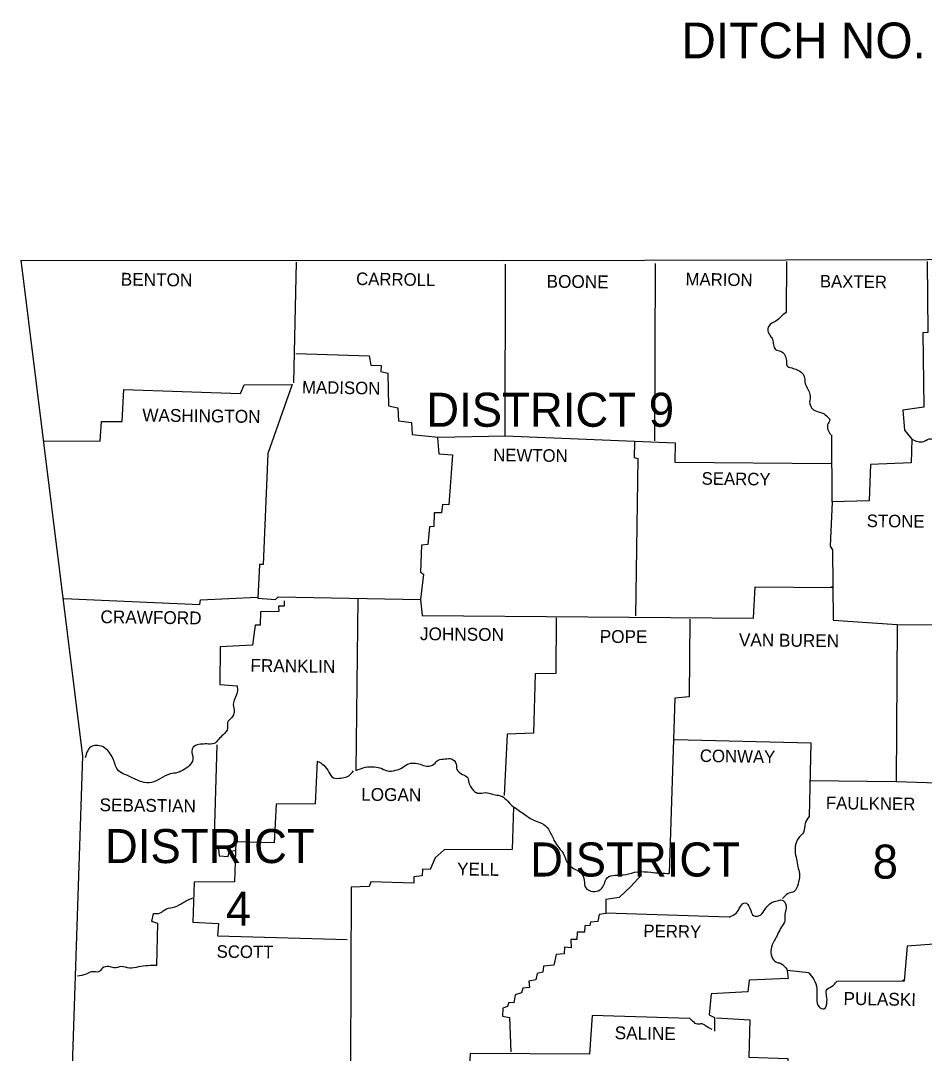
# Model space of a CAD drawing. Extents: x 191 to 3403, y 68 to 2102.
# Drawn here: x 2703.7 to 2999.8, y 1696.4 to 2035 of the extents above; entities that cross this region are included whole.
import ezdxf

# ---------------------------------------------------------------- set-up
doc = ezdxf.new("R2010")
doc.units = 0
for name, color, linetype in [('1', 7, 'Continuous'), ('2', 7, 'Continuous'), ('3', 7, 'Continuous'), ('R_Border', 7, 'Continuous')]:
    doc.layers.add(name, color=color, linetype=linetype)

msp = doc.modelspace()

# ---------------------------------------------------------------- linework, layer by layer
at = {"layer": '1'}
for points in [[(2703.71, 1956.42), (2861.92, 1956.32), (3000.75, 1956.61), (3164.54, 1959.16), (3240.46, 1960.92)], [(2703.71, 1956.42), (2723.96, 1793.81), (2715.15, 1528.37)], [(2794.01, 1955.83), (2793.13, 1916.21)], [(2793.82, 1925.89), (2817.89, 1925.11), (2818.47, 1921.98), (2821.8, 1921.88), (2821.7, 1919.92), (2824.05, 1919.34), (2824.25, 1908.67), (2827.28, 1907.99), (2827.48, 1903.78), (2831.78, 1903.19), (2831.98, 1899.28), (2840.49, 1898.4), (2862.4, 1898.89), (2862.6, 1955.15)], [(2911.62, 1955.34), (2911.33, 1897.22)], [(2954.67, 1956.03), (2954.47, 1939.3)], [(3000.75, 1956.03), (3000.95, 1932.74), (2999.28, 1932.64), (2999.58, 1908.28), (2992.73, 1907.3), (2993.32, 1900.75), (2995.66, 1897.71), (2995.47, 1889.98), (2982.16, 1889.5), (2981.67, 1877.56), (2969.54, 1877.17), (2968.95, 1862.69), (2969.64, 1861.51), (2969.93, 1838.42), (2990.87, 1837.05), (2990.58, 1785.49), (3007.21, 1785), (3007.21, 1732.56), (2994.1, 1731.58), (2993.12, 1720.04), (2971.11, 1719.94)], [(2711.44, 1897.22), (2729.73, 1897.13), (2730.22, 1903.58), (2736.97, 1903.58), (2737.56, 1914.05), (2775.72, 1912.68), (2776.89, 1915.62), (2792.64, 1915.72), (2784.72, 1893.02), (2783.15, 1856.72), (2781.98, 1856.62), (2781.39, 1845.66), (2787.17, 1845.17), (2788.05, 1846.05), (2834.72, 1845.17), (2835.21, 1839.99)], [(2840.29, 1898.2), (2840.68, 1892.92), (2845.18, 1892.63), (2844.01, 1876.19), (2841.96, 1876.29), (2841.56, 1873.65), (2839.22, 1873.65), (2839.12, 1869.14), (2837.65, 1869.05), (2837.16, 1863.27), (2835.01, 1862.98), (2834.72, 1854.17), (2835.69, 1853.49), (2834.72, 1845.17)], [(2862.4, 1898.89), (2918.17, 1896.54), (2918.08, 1890.18), (2969.25, 1889.79)], [(2904.77, 1896.83), (2904.67, 1891.75), (2905.94, 1891.45), (2905.16, 1839.79)], [(2969.54, 1877.17), (2969.44, 1899.18)], [(2835.21, 1839.99), (2943.81, 1839.11), (2944.3, 1849.38), (2969.54, 1849.09)], [(2969.25, 1849.19), (2969.54, 1849.48)], [(2717.89, 1845.56), (2762.41, 1843.51), (2762.61, 1845.08), (2781.2, 1845.96)], [(2814.17, 1845.56), (2813.48, 1789.11)], [(2790, 1844.78), (2790, 1843.02), (2788.14, 1843.02), (2788.24, 1841.26), (2782.27, 1841.16), (2782.18, 1836.76), (2780.51, 1836.76), (2779.63, 1830.2), (2769.06, 1829.71), (2768.97, 1817.29), (2774.64, 1816.9)], [(2879.14, 1839.21), (2879.04, 1820.91), (2872.29, 1820.81), (2871.7, 1801.34), (2863.09, 1801.05), (2862.11, 1780.89)], [(2922.97, 1838.72), (2922.77, 1813.28), (2918.08, 1812.89), (2916.22, 1755.36)], [(2990.87, 1837.05), (3041.16, 1836.76), (3045.46, 1838.81), (3045.17, 1800.56), (3042.24, 1799.29), (3039.59, 1797.04), (3038.71, 1796.16), (3038.62, 1785.2), (3006.62, 1785.2)], [(2917.88, 1799.29), (2962.59, 1798.21), (2962.01, 1774.04)], [(2767.99, 1797.53), (2767.01, 1763.87), (2768.48, 1763.48), (2768.77, 1761.13), (2771.71, 1760.93), (2772, 1762.6), (2774.35, 1762.99)], [(2800.86, 1792.24), (2800.18, 1778.25), (2787.46, 1778.15), (2786.77, 1765.43), (2774.15, 1765.73), (2773.76, 1752.62), (2760.55, 1752.52), (2760.16, 1739.41), (2768.48, 1738.92), (2768.18, 1734.91), (2810.65, 1733.73)], [(2962.1, 1785.88), (2990.58, 1785.49)], [(2865.14, 1777.27), (2864.75, 1763.18), (2842.45, 1763.09), (2839.51, 1760.54), (2837.85, 1756.63), (2835.4, 1756.82), (2835.3, 1754.57), (2832.47, 1754.28), (2832.56, 1752.22), (2818.38, 1752.62), (2817.89, 1751.05), (2812.02, 1750.86), (2811.82, 1693.62)], [(2907.12, 1754.96), (2903.6, 1751.15), (2899.78, 1747.53), (2895.38, 1746.84), (2895.38, 1742.25), (2893.22, 1741.95), (2892.83, 1739.6), (2890.39, 1739.41), (2890.19, 1738.33), (2888.53, 1738.23), (2888.43, 1736.18), (2886.08, 1736.08), (2885.89, 1733.73), (2883.93, 1733.73), (2884.03, 1730.99), (2881.88, 1731.19), (2881.78, 1729.04), (2879.14, 1728.84), (2878.35, 1725.32), (2875.03, 1725.03), (2874.73, 1723.07), (2872.97, 1722.58), (2872.48, 1720.52), (2870.23, 1720.04), (2870.43, 1717.98), (2868.18, 1717.78), (2867.79, 1716.22), (2865.73, 1715.63), (2865.24, 1712.99), (2863.68, 1713.09), (2863.19, 1711.72), (2861.72, 1711.23), (2861.62, 1708.59), (2863.87, 1708.2), (2864.26, 1696.85)], [(2748.32, 1725.22), (2748.62, 1739.02), (2746.66, 1739.6), (2747.25, 1742.25)], [(2935.79, 1741.07), (2895.47, 1742.34)], [(2961.91, 1722.77), (2954.86, 1723.56), (2955.16, 1720.92), (2942.34, 1720.43), (2941.95, 1716.61), (2929.91, 1715.93), (2929.23, 1709.08), (2930.99, 1708.2), (2930.99, 1703.7)], [(2992.63, 1720.13), (2993.12, 1720.62)], [(2922.97, 1707.81), (2890.97, 1708.78), (2890.09, 1696.16), (2850.96, 1696.36), (2850.76, 1692.15)], [(2931.68, 1708.1), (2942.63, 1707.41), (2942.24, 1695.18), (2955.06, 1694.69), (2955.26, 1684.03), (2961.32, 1683.54), (2961.32, 1681.68), (2967, 1681.29), (2967.19, 1674.44), (2980.11, 1674.44), (2980.5, 1667.69), (2992.44, 1667.1), (2992.34, 1654.38)]]:
    msp.add_lwpolyline(points, dxfattribs=at)
for points in [[(2954.47, 1939.3), (2952.71, 1937.83), (2951.15, 1936.46), (2948.8, 1934.8), (2948.5, 1933.23), (2949.29, 1931.66), (2950.07, 1930.39), (2950.36, 1928.63), (2951.05, 1927.16), (2952.71, 1926.58), (2954.08, 1925.31), (2954.57, 1923.54), (2954.77, 1921.88), (2956.33, 1921.1), (2958.09, 1920.51), (2959.76, 1919.34), (2960.54, 1917.87), (2960.73, 1916.01), (2961.42, 1914.54), (2962.2, 1912.78), (2962.4, 1911.31), (2962.2, 1909.85), (2962.59, 1908.48), (2963.87, 1907.11), (2966.12, 1906.42), (2967.68, 1905.44), (2968.76, 1904.07), (2968.07, 1902.41), (2968.17, 1900.94), (2969.05, 1899.18)], [(2995.66, 1897.71), (2999.58, 1897.03), (3001.93, 1897.91), (3003.59, 1895.37), (3004.47, 1893.41), (3005.94, 1890.57), (3008.29, 1889.69), (3010.05, 1888.13), (3010.05, 1886.46), (3008.48, 1884.9), (3007.31, 1883.33), (3007.7, 1881.47), (3008.09, 1878.93), (3008.09, 1876.48), (3007.5, 1874.23), (3007.01, 1872.18), (3007.5, 1870.42), (3009.36, 1870.71), (3011.32, 1872.18), (3013.37, 1872.18), (3015.33, 1871.1), (3017.38, 1869.24), (3019.44, 1869.63), (3021.1, 1870.12), (3023.45, 1870.81), (3025.11, 1869.93), (3026.58, 1868.75), (3028.34, 1866.89), (3030.01, 1865.72), (3032.16, 1864.64), (3034.8, 1863.96), (3037.25, 1862.3), (3037.64, 1859.46), (3037.54, 1857.01), (3037.34, 1853.98), (3037.15, 1850.65), (3037.44, 1847.42), (3038.52, 1845.27), (3039.89, 1842.73), (3040.28, 1840.38), (3040.18, 1836.66)], [(2774.64, 1816.9), (2774.64, 1814.84), (2773.86, 1812.69), (2773.37, 1810.83), (2773.66, 1808.39), (2772.78, 1806.43), (2771.51, 1804.86), (2771.51, 1802.91), (2770.04, 1800.85), (2768.48, 1799.29), (2767.11, 1798.01), (2764.66, 1797.82), (2762.61, 1797.72), (2760.55, 1797.04), (2759.77, 1795.57), (2760.16, 1793.32), (2759.38, 1791.17), (2757.32, 1789.5), (2755.07, 1788.43), (2752.73, 1788.03), (2749.5, 1786.47), (2746.56, 1785.2), (2743.43, 1785.39), (2740.5, 1786.66), (2737.85, 1787.84), (2735.8, 1789.01), (2734.14, 1792.63), (2733.06, 1794.59), (2731.2, 1796.55), (2728.95, 1797.33), (2727.09, 1797.13), (2724.84, 1793.32)], [(2800.86, 1792.24), (2803.02, 1790.87), (2804.68, 1788.62), (2806.15, 1786.76), (2808.59, 1786.66), (2810.55, 1787.06), (2812.8, 1789.01)], [(2813.48, 1789.11), (2816.71, 1790.19), (2819.06, 1790.38), (2821.41, 1789.99), (2823.86, 1789.01), (2826.5, 1789.21), (2828.45, 1789.89), (2830.41, 1791.17), (2832.56, 1791.56), (2834.62, 1791.17), (2836.77, 1790.58), (2839.12, 1791.26), (2840.49, 1792.54), (2842.84, 1792.93), (2844.89, 1792.93), (2846.36, 1791.26), (2846.65, 1789.5), (2848.51, 1787.84), (2850.17, 1786.76), (2850.66, 1784.71), (2851.54, 1783.24), (2852.43, 1782.26), (2853.7, 1781.67), (2855.85, 1781.87), (2859.18, 1781.19), (2861.33, 1780.7), (2863.29, 1779.03), (2865.14, 1777.27)], [(2865.14, 1777.27), (2868.57, 1774.92), (2871.8, 1772.87), (2875.12, 1771.4), (2876.98, 1769.25), (2878.65, 1765.92), (2880.02, 1763.87), (2881.78, 1761.32), (2883.05, 1758.49), (2885.1, 1756.92), (2887.26, 1755.55), (2888.33, 1753.11), (2888.82, 1750.66), (2891.17, 1749.49), (2893.42, 1749.97), (2894.69, 1751.44), (2895.87, 1753.99), (2898.51, 1754.77), (2901.93, 1755.06), (2905.85, 1755.94), (2910.15, 1755.75), (2916.22, 1755.36)], [(2962.01, 1774.04), (2960.73, 1771.79), (2960.15, 1768.86), (2958.58, 1767), (2957.6, 1764.85), (2957.51, 1762.01), (2958, 1759.47), (2958.48, 1757.02), (2958.88, 1754.77), (2958.39, 1751.93), (2957.11, 1749.49), (2955.16, 1748.8), (2953.3, 1747.14)], [(2747.25, 1742.25), (2749.4, 1742.44), (2751.45, 1743.81), (2754.19, 1744.4), (2756.93, 1745.87), (2760.36, 1747.43)], [(2935.79, 1741.07), (2938.23, 1742.44), (2939.5, 1744.5), (2941.07, 1745.77), (2942.63, 1744.01), (2944, 1741.46), (2945.47, 1741.46), (2947.33, 1743.22), (2948.5, 1744.79), (2949.97, 1745.96), (2951.54, 1746.45), (2953.2, 1746.65), (2954.47, 1744.79), (2954.08, 1741.85), (2954.08, 1739.9), (2953.01, 1737.84), (2951.83, 1735.69), (2950.56, 1733.24), (2949.58, 1730.6), (2949.78, 1728.06), (2951.15, 1726.39), (2952.71, 1725.91), (2954.86, 1723.75)], [(2748.32, 1725.22), (2745.49, 1725.12), (2742.26, 1724.73), (2739.32, 1724.34), (2736.68, 1724.83), (2734.23, 1724.44), (2732.57, 1724.83), (2730.52, 1724.34), (2729.34, 1723.17), (2726.9, 1723.17), (2725.13, 1722.38), (2722.3, 1721.7)], [(2961.91, 1722.77), (2963.57, 1720.62), (2964.55, 1717.69), (2964.55, 1714.36), (2965.33, 1711.62), (2966.9, 1711.03), (2967.88, 1713.38), (2967.68, 1715.73), (2967.68, 1717.1), (2969.34, 1718.27), (2971.11, 1719.94)], [(2930.31, 1704.19), (2928.45, 1705.16), (2926.98, 1706.04), (2925.41, 1705.95), (2924.14, 1706.73), (2922.97, 1707.81)]]:
    msp.add_spline(points, degree=3, dxfattribs=at)

# ---------------------------------------------------------------- texts
at = {"layer": '2'}
for s, height, rotation, p in [('BENTON', 4.207, 359.2527, (2736.48, 1948.1)), ('CARROLL', 4.109, 359.1481, (2813.58, 1948.3)), ('BOONE', 4.207, 359.4001, (2876, 1947.42)), ('MARION', 4.109, 359.1854, (2921.5, 1948.2)), ('BAXTER', 4.109, 359.2559, (2965.53, 1947.51)), ('MADISON', 4.109, 359.0906, (2795.87, 1912.78)), ('WASHINGTON', 4.206, 359.232, (2743.53, 1903.58)), ('NEWTON', 4.109, 359.2717, (2858.49, 1890.57)), ('SEARCY', 4.108, 359.2527, (2926.78, 1882.84)), ('STONE', 4.108, 359.4001, (2980.89, 1868.95)), ('CRAWFORD', 4.206, 359.2771, (2729.83, 1837.44)), ('JOHNSON', 4.207, 359.3514, (2834.52, 1831.87)), ('POPE', 4.207, 359.6155, (2893.42, 1830.99)), ('VAN BUREN', 4.207, 359.3508, (2939.01, 1829.91)), ('FRANKLIN', 4.207, 359.1815, (2778.95, 1821.5)), ('CONWAY', 4.108, 359.0371, (2926.2, 1791.95)), ('LOGAN', 4.207, 359.3969, (2815.25, 1779.23)), ('SEBASTIAN', 4.206, 359.2816, (2729.54, 1775.8)), ('FAULKNER', 4.109, 359.2486, (2967.49, 1776.49)), ('YELL', 4.207, 359.1987, (2846.65, 1754.77)), ('PERRY', 4.109, 359.0858, (2907.71, 1734.52)), ('SCOTT', 4.109, 359.4063, (2767.89, 1727.76)), ('PULASKI', 4.207, 359.053, (2973.26, 1712.31)), ('SALINE', 4.207, 359.1491, (2898.31, 1701.05))]:
    msp.add_text(s, height=height, rotation=rotation, dxfattribs=at).set_placement(p)
at = {"layer": '3'}
for s, height, p in [('DISTRICT 9', 11.154, (2836.57, 1901.82)), ('DISTRICT', 11.154, (2731.3, 1758.78)), ('DISTRICT', 11.154, (2870.62, 1754.38)), ('8', 11.15, (2982.85, 1753.69)), ('4', 11.15, (2770.92, 1738.23))]:
    msp.add_text(s, height=height, dxfattribs=at).set_placement(p)
at = {"layer": 'R_Border'}
msp.add_text('DITCH NO. 30 STR. & APPRS. (BLYTHEVILLE) (S)', height=11.724, dxfattribs=at).set_placement((2920.15, 2022.61))

doc.saveas('drawing.dxf')
